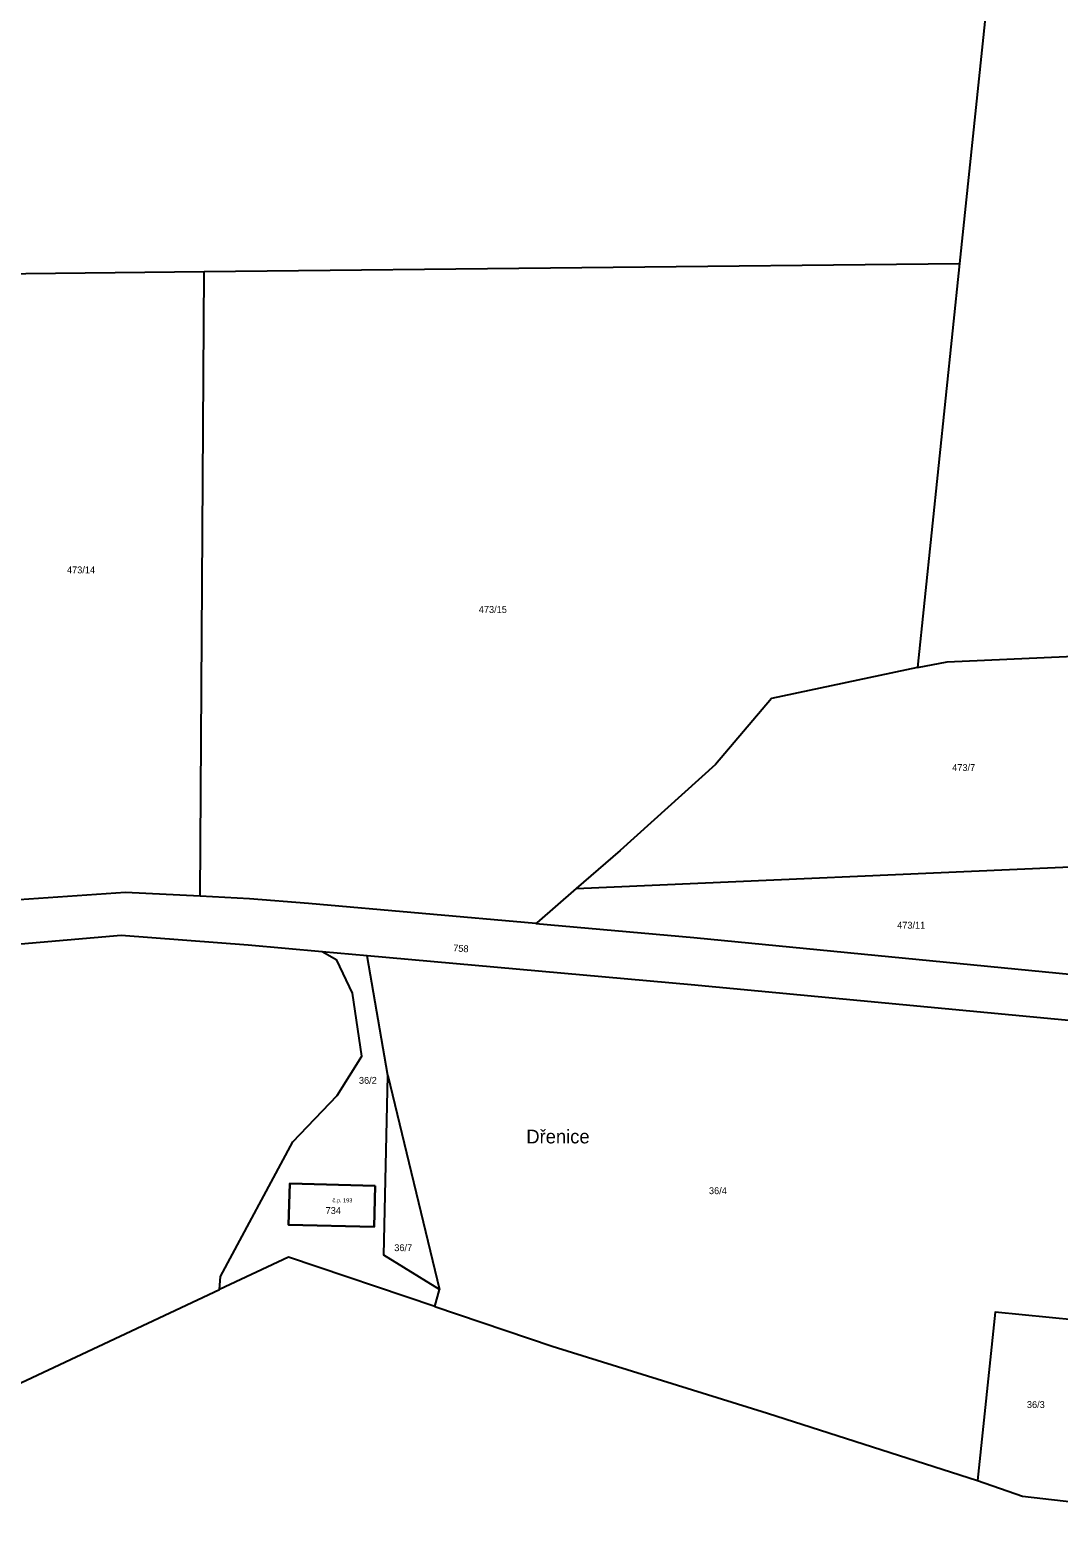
# Model space of a CAD drawing. Extents: x -887272 to -880188, y -1026687 to -1021896.
# Drawn here: x -883313.1 to -883058.7, y -1024089.6 to -1023716.8 of the extents above; entities that cross this region are included whole.
import ezdxf

# ---------------------------------------------------------------- set-up
doc = ezdxf.new("R2010")
doc.units = 0
for name, color, linetype in [('Definiční body', 7, 'Continuous'), ('Hranice parcel', 7, 'Continuous'), ('Parcelní čísla', 7, 'Continuous'), ('Polygon budovy', 7, 'Continuous'), ('Pop  PČ popisy', 7, 'Continuous')]:
    doc.layers.add(name, color=color, linetype=linetype)

msp = doc.modelspace()

# ---------------------------------------------------------------- linework, layer by layer
at = {"layer": 'Hranice parcel'}
for p, q in [((-883270.1, -1023776.5), (-883083.3, -1023774.48)), ((-883083.3, -1023774.48), (-883093.7, -1023874.44)), ((-883325.3, -1023777.1), (-883270.1, -1023776.5)), ((-883271.05, -1023930.97), (-883270.1, -1023776.5)), ((-883178.1, -1023929.02), (-883026.61, -1023922.44)), ((-883178.1, -1023929.02), (-883187.84, -1023937.5)), ((-883187.84, -1023937.5), (-883188.08, -1023937.71)), ((-883229.75, -1023945.68), (-883240.89, -1023944.68)), ((-883224.67, -1023975.29), (-883229.75, -1023945.68)), ((-883224.67, -1023975.29), (-883211.85, -1024028.22)), ((-883213.06, -1024032.41), (-883211.85, -1024028.22))]:
    msp.add_line(p, q, dxfattribs=at)
for points in [[(-883061.09, -1023541.51), (-883058.83, -1023540.64), (-883083.3, -1023774.48)], [(-883093.7, -1023874.44), (-883086.38, -1023873.01), (-883023.64, -1023870.22)], [(-883093.7, -1023874.44), (-883129.75, -1023882.03), (-883143.66, -1023898.37), (-883167.16, -1023919.64), (-883178.1, -1023929.02)], [(-883271.05, -1023930.97), (-883289.54, -1023930.04), (-883325.44, -1023932.53)], [(-883188.08, -1023937.71), (-883244.27, -1023932.76), (-883258.84, -1023931.58), (-883271.05, -1023930.97)], [(-883188.08, -1023937.71), (-883148.98, -1023941.16), (-883038.36, -1023951.95)], [(-883240.89, -1023944.68), (-883259.18, -1023943.04), (-883290.58, -1023940.7), (-883342.16, -1023945.12), (-883390.28, -1023964.24)], [(-883266.28, -1024028.21), (-883265.99, -1024024.94), (-883248.11, -1023991.69), (-883237.16, -1023980.19), (-883231.07, -1023970.46), (-883233.36, -1023954.91), (-883237.28, -1023946.74), (-883240.89, -1023944.68)], [(-883024.78, -1023962.34), (-883038.88, -1023963.34), (-883149.62, -1023952.88), (-883229.75, -1023945.68)], [(-883211.85, -1024028.22), (-883225.63, -1024019.74), (-883224.67, -1023975.29)], [(-883227.8, -1024002.55), (-883228.06, -1024012.74), (-883249.17, -1024012.19), (-883248.91, -1024002.02), (-883227.8, -1024002.55)], [(-883213.06, -1024032.41), (-883249.22, -1024020.2), (-883266.28, -1024028.21)], [(-883469.7, -1024089.6), (-883449.24, -1024083.76), (-883375.54, -1024061.88), (-883326.34, -1024056.38), (-883266.28, -1024028.21)], [(-883213.06, -1024032.41), (-883184.04, -1024042.2), (-883130.8, -1024058.74), (-883078.86, -1024075.42)], [(-883054.46, -1024035.79), (-883074.51, -1024033.76), (-883078.86, -1024075.42)], [(-883078.86, -1024075.42), (-883067.68, -1024079.26), (-883047.64, -1024081.6)]]:
    msp.add_lwpolyline(points, dxfattribs=at)
at = {"layer": 'Polygon budovy'}
msp.add_lwpolyline([(-883227.8, -1024002.55), (-883248.91, -1024002.02), (-883249.17, -1024012.19), (-883228.06, -1024012.74)], close=True, dxfattribs=at)

# ---------------------------------------------------------------- texts
at = {"layer": 'Definiční body'}
msp.add_text('č.p. 193', height=1, dxfattribs=at).set_placement((-883238.33, -1024006.65))
at = {"layer": 'Parcelní čísla'}
for s, p in [('473/14', (-883303.99, -1023851.12)), ('473/15', (-883202.16, -1023860.91)), ('473/7', (-883085.1, -1023899.99)), ('473/11', (-883098.71, -1023938.97)), ('36/2', (-883231.8, -1023977.33)), ('36/4', (-883145.24, -1024004.62)), ('734', (-883240.03, -1024009.52)), ('36/7', (-883223.06, -1024018.71)), ('36/3', (-883066.63, -1024057.5))]:
    msp.add_text(s, height=1.7, dxfattribs=at).set_placement(p)
msp.add_text('758', height=1.7, rotation=356, dxfattribs=at).set_placement((-883208.54, -1023944.57))
at = {"layer": 'Pop  PČ popisy'}
msp.add_text('Dřenice', height=3.4, dxfattribs=at).set_placement((-883190.41, -1023992.07))

doc.saveas('drawing.dxf')
